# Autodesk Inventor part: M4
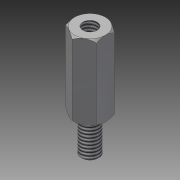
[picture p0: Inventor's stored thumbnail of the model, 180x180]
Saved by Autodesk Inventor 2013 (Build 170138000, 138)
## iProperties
Created: 2012-08
Part Number: M4
Material: Stahl
Document SubType Name: Modeling
Designer: rYan
Density: 7.85 g/cm^3
Author: rYan
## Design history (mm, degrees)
derived "Abstandsbolzen Typ B.ipt"
feature "Volumenkörper1::Abstandsbolzen Typ B.ipt"
tag "Bezeichnung1"
node "Volumenkörper1"
other parameters: "SW" = 7, "L" = 17, "d2" = 0, "l_" = 9, "d9" = 118 deg, "GA_" = 4, "A_" = 8, "d13" = 0, "d17" = 0.25, "d20" = 45 deg
